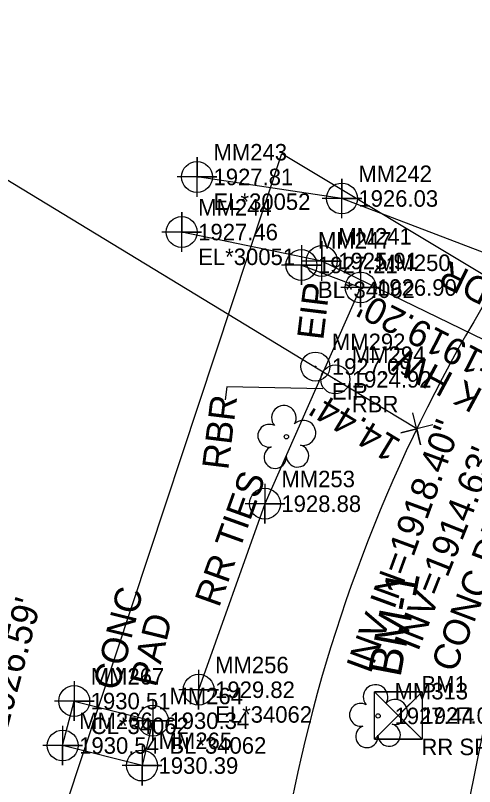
# Model space of a CAD drawing. Extents: x 1004514 to 1005247, y 553695 to 554706.
# Drawn here: x 1004934 to 1005003.6, y 554190.9 to 554307.9 of the extents above; entities that cross this region are included whole.
import ezdxf

# ---------------------------------------------------------------- set-up
doc = ezdxf.new("R2010")
doc.units = 0
for name, color, linetype in [('CTL Vertical Benchmark CELL', 7, 'Continuous'), ('CTL Vertical Benchmark Cogo Comment', 7, 'Continuous'), ('CTL Vertical Benchmark Cogo Elevation', 7, 'Continuous'), ('CTL Vertical Benchmark Cogo Number', 7, 'Continuous'), ('CTL Vertical Benchmark Text', 7, 'Continuous'), ('Exist Other Culture Area Outline', 7, 'Continuous'), ('Exist Other Culture Area Outline Cogo Comment', 7, 'Continuous'), ('Exist Other Culture Area Outline Cogo Elevation', 7, 'Continuous'), ('Exist Other Culture Area Outline Cogo Number', 7, 'Continuous'), ('Exist Other Culture Area Outline Cogo Point CELL', 7, 'Continuous'), ('Exist Other Culture Area Outline Text', 7, 'Continuous'), ('Exist Property Corner CELL', 7, 'Continuous'), ('Exist Property Iron Pin CELL', 7, 'Continuous'), ('Exist Property Iron Pin Cogo Comment', 7, 'Continuous'), ('Exist Property Iron Pin Cogo Elevation', 7, 'Continuous'), ('Exist Property Iron Pin Cogo Number', 7, 'Continuous'), ('Exist Property Iron Pin Leader', 7, 'Continuous'), ('Exist Property Iron Pin Text', 7, 'Continuous'), ('Exist Property Line', 7, 'Continuous'), ('Exist Property Line Text', 7, 'Continuous'), ('Exist Right of Way Line', 7, 'Continuous'), ('Exist Roads EOP', 7, 'Continuous'), ('Exist Roads Soil', 7, 'Continuous'), ('Exist Roads Soil Cogo Comment', 7, 'Continuous'), ('Exist Roads Soil Cogo Elevation', 7, 'Continuous'), ('Exist Roads Soil Cogo Number', 7, 'Continuous'), ('Exist Roads Soil Cogo Point CELL', 7, 'Continuous'), ('Exist Roads Soil Text', 7, 'Continuous'), ('Exist Structure Major Bridge WW Text', 7, 'Continuous'), ('Exist Structure Minor Drop Inlet Text', 7, 'Continuous'), ('Exist Structure Minor Drop Inlet Top Elevation', 7, 'Continuous'), ('Exist Structure Minor Pipes CMP 30 Inch Invert', 7, 'Continuous'), ('Exist Structure Minor Pipes RCP 15 Inch Invert', 7, 'Continuous'), ('Exist Utilities Telephone UG FO SUE LOS C', 7, 'Continuous'), ('Exist Vegetation Tree CELL', 7, 'Continuous'), ('Exist Vegetation Tree Cogo Elevation', 7, 'Continuous'), ('Exist Vegetation Tree Cogo Number', 7, 'Continuous'), ('Old_Level_3', 7, 'Continuous')]:
    doc.layers.add(name, color=color, linetype=linetype)

msp = doc.modelspace()

# ---------------------------------------------------------------- linework, layer by layer
at = {"layer": 'CTL Vertical Benchmark CELL'}
msp.add_line((1004992.06, 554201.69), (1004992.06, 554201.69), dxfattribs=at)
msp.add_lwpolyline([(1004988.46, 554205.27), (1004995.65, 554205.27), (1004995.65, 554198.09), (1004988.46, 554198.09)], close=True, dxfattribs=at)
for points in [[(1004995.65, 554205.27), (1004988.46, 554198.09), (1004992.06, 554201.68), (1004995.65, 554198.09), (1004988.46, 554205.27)], [(1004992.06, 554201.68), (1004995.65, 554205.27), (1004988.46, 554205.27), (1004992.06, 554201.68)], [(1004992.06, 554201.68), (1004988.46, 554198.09), (1004995.65, 554198.09), (1004992.06, 554201.68)]]:
    msp.add_lwpolyline(points, dxfattribs=at)
at = {"layer": 'Exist Other Culture Area Outline'}
for points in [[(1004977.38, 554270.02), (1004986.34, 554266.61), (1004971.84, 554233.82), (1004961.8, 554205.61)], [(1004954.87, 554200.91), (1004953.22, 554194.11), (1004941.19, 554197.15), (1004942.94, 554203.89), (1004954.87, 554200.91)]]:
    msp.add_lwpolyline(points, dxfattribs=at)
at = {"layer": 'Exist Other Culture Area Outline Cogo Point CELL'}
for points in [[(1004977.38, 554273.02), (1004977.38, 554267.02), (1004977.38, 554270.02), (1004980.38, 554270.02), (1004974.38, 554270.02)], [(1004986.34, 554269.61), (1004986.34, 554263.61), (1004986.34, 554266.61), (1004989.34, 554266.61), (1004983.34, 554266.61)], [(1004971.84, 554236.82), (1004971.84, 554230.82), (1004971.84, 554233.82), (1004974.84, 554233.82), (1004968.84, 554233.82)], [(1004961.8, 554208.61), (1004961.8, 554202.61), (1004961.8, 554205.61), (1004964.8, 554205.61), (1004958.8, 554205.61)], [(1004942.94, 554206.89), (1004942.94, 554200.89), (1004942.94, 554203.89), (1004945.94, 554203.89), (1004939.94, 554203.89)], [(1004954.87, 554203.91), (1004954.87, 554197.91), (1004954.87, 554200.91), (1004957.87, 554200.91), (1004951.87, 554200.91)], [(1004941.19, 554200.15), (1004941.19, 554194.15), (1004941.19, 554197.15), (1004944.19, 554197.15), (1004938.19, 554197.15)], [(1004953.22, 554197.11), (1004953.22, 554191.11), (1004953.22, 554194.11), (1004956.22, 554194.11), (1004950.22, 554194.11)]]:
    msp.add_lwpolyline(points, dxfattribs=at)
for centre in [(1004977.38, 554270.02), (1004986.34, 554266.61), (1004971.84, 554233.82), (1004961.8, 554205.61), (1004942.94, 554203.89), (1004954.87, 554200.91), (1004941.19, 554197.15), (1004953.22, 554194.11)]:
    msp.add_circle(centre, 2.34, dxfattribs=at)
at = {"layer": 'Exist Property Corner CELL'}
msp.add_line((1004994.85, 554245.18), (1004994.85, 554245.18), dxfattribs=at)
msp.add_lwpolyline([(1004997.28, 554245.77), (1004992.42, 554244.59), (1004994.85, 554245.18), (1004995.44, 554242.75), (1004994.26, 554247.61)], dxfattribs=at)
at = {"layer": 'Exist Property Iron Pin CELL'}
for centre, radius in [((1004979.49, 554254.62), 2.2), ((1004979.49, 554254.62), 0.0707), ((1004982.51, 554252.68), 2.2), ((1004982.51, 554252.68), 0.0707)]:
    msp.add_circle(centre, radius, dxfattribs=at)
at = {"layer": 'Exist Property Iron Pin Leader'}
msp.add_lwpolyline([(1004980.63, 554251.22), (1004966.05, 554251.54), (1004965.81, 554249.57)], dxfattribs=at)
at = {"layer": 'Exist Property Line'}
for p, q in [((1004982.51, 554252.68), (1004850.41, 554332.98)), ((1004994.85, 554245.18), (1004982.51, 554252.68))]:
    msp.add_line(p, q, dxfattribs=at)
at = {"layer": 'Exist Right of Way Line'}
msp.add_arc((1005209.2, 554141.74), 238, 143.2645, 181.1585, dxfattribs=at)
at = {"layer": 'Exist Roads EOP'}
msp.add_spline([(1005026.38, 554243.67), (1005017.05, 554225.79), (1005004.48, 554185.7), (1005001.44, 554147.87), (1005001.03, 554103.61), (1005002.79, 554054.52)], degree=3, dxfattribs=at)
at = {"layer": 'Exist Roads Soil'}
for points in [[(1005035.48, 554262), (1005019.75, 554266.28), (1004983.51, 554280.11), (1004961.55, 554283.38)], [(1005026.92, 554247.39), (1005013.88, 554254.38), (1004980.46, 554270.63), (1004959.23, 554275.02)]]:
    msp.add_lwpolyline(points, dxfattribs=at)
at = {"layer": 'Exist Roads Soil Cogo Point CELL'}
for points in [[(1004961.55, 554280.38), (1004961.55, 554286.38), (1004961.55, 554283.38), (1004964.55, 554283.38), (1004958.55, 554283.38)], [(1004983.51, 554277.11), (1004983.51, 554283.11), (1004983.51, 554280.11), (1004986.51, 554280.11), (1004980.51, 554280.11)], [(1004959.23, 554272.02), (1004959.23, 554278.02), (1004959.23, 554275.02), (1004962.23, 554275.02), (1004956.23, 554275.02)], [(1004980.46, 554267.63), (1004980.46, 554273.63), (1004980.46, 554270.63), (1004983.46, 554270.63), (1004977.46, 554270.63)]]:
    msp.add_lwpolyline(points, dxfattribs=at)
for centre in [(1004961.55, 554283.38), (1004983.51, 554280.11), (1004959.23, 554275.02), (1004980.46, 554270.63)]:
    msp.add_circle(centre, 2.34, dxfattribs=at)
at = {"layer": 'Exist Utilities Telephone UG FO SUE LOS C'}
msp.add_lwpolyline([(1004993.35, 553880.97), (1004999.91, 553935.31), (1005000.5, 553983.29), (1004999.33, 554031.27), (1004996.57, 554081.46), (1004996.43, 554140.05), (1004998.71, 554168.32), (1005009.15, 554220.25), (1005037.11, 554266.75), (1005065.19, 554302.19)], dxfattribs=at)
at = {"layer": 'Exist Vegetation Tree CELL'}
for p, q in [((1004975.1, 554243.98), (1004975.1, 554243.98)), ((1004988.99, 554201.64), (1004988.99, 554201.64))]:
    msp.add_line(p, q, dxfattribs=at)
for centre in [(1004975.1, 554243.98), (1004988.99, 554201.64)]:
    msp.add_circle(centre, 0.326, dxfattribs=at)
for centre, radius, start, end in [((1004974.72, 554246.85), 1.86, 330.1651, 219.7134), ((1004977.65, 554244.57), 1.9, 257.1011, 134.1999), ((1004972.5, 554244.13), 1.73, 62.6636, 279.3457), ((1004976.78, 554241.08), 1.7, 181.2822, 74.56), ((1004973.4, 554240.86), 1.69, 111.5671, 6.231), ((1004988.61, 554204.52), 1.86, 330.1651, 219.7134), ((1004991.54, 554202.23), 1.9, 257.1011, 134.1999), ((1004986.39, 554201.8), 1.73, 62.6636, 279.3457), ((1004987.29, 554198.52), 1.69, 111.5671, 6.231), ((1004990.67, 554198.74), 1.7, 181.2822, 74.56)]:
    msp.add_arc(centre, radius, start, end, dxfattribs=at)
at = {"layer": 'Old_Level_3'}
for p, q in [((1004908.04, 554086.33), (1004974.39, 554286.95)), ((1004974.39, 554286.95), (1005076.11, 554225.78))]:
    msp.add_line(p, q, dxfattribs=at)

# ---------------------------------------------------------------- texts
at = {"layer": 'CTL Vertical Benchmark Cogo Comment'}
msp.add_text('RR SPIKE IN BASE OF DBL 16" FIR', height=2.5, dxfattribs=at).set_placement((1004995.56, 554195.69))
at = {"layer": 'CTL Vertical Benchmark Cogo Elevation'}
msp.add_text('1927.07', height=2.5, dxfattribs=at).set_placement((1004995.56, 554200.44))
at = {"layer": 'CTL Vertical Benchmark Cogo Number'}
msp.add_text('BM1', height=2.5, dxfattribs=at).set_placement((1004995.56, 554205.19))
at = {"layer": 'CTL Vertical Benchmark Text'}
msp.add_text('BM-1', height=5, rotation=79.2045, dxfattribs=at).set_placement((1004992.36, 554207.37))
at = {"layer": 'Exist Other Culture Area Outline Cogo Comment'}
for s, p in [('BL*34062', (1004979.88, 554265.02)), ('EL*34062', (1004964.3, 554200.61)), ('CL*34062', (1004945.44, 554198.89)), ('BL*34062', (1004957.37, 554195.91))]:
    msp.add_text(s, height=2.5, dxfattribs=at).set_placement(p)
at = {"layer": 'Exist Other Culture Area Outline Cogo Elevation'}
for s, p in [('1927.21', (1004979.88, 554268.77)), ('1926.90', (1004988.84, 554265.36)), ('1928.88', (1004974.34, 554232.57)), ('1929.82', (1004964.3, 554204.36)), ('1930.51', (1004945.44, 554202.64)), ('1930.34', (1004957.37, 554199.66)), ('1930.54', (1004943.69, 554195.9)), ('1930.39', (1004955.72, 554192.86))]:
    msp.add_text(s, height=2.5, dxfattribs=at).set_placement(p)
at = {"layer": 'Exist Other Culture Area Outline Cogo Number'}
for s, p in [('MM247', (1004979.88, 554272.52)), ('MM250', (1004988.84, 554269.11)), ('MM253', (1004974.34, 554236.32)), ('MM256', (1004964.3, 554208.11)), ('MM267', (1004945.44, 554206.39)), ('MM264', (1004957.37, 554203.41)), ('MM266', (1004943.69, 554199.65)), ('MM265', (1004955.72, 554196.61))]:
    msp.add_text(s, height=2.5, dxfattribs=at).set_placement(p)
at = {"layer": 'Exist Other Culture Area Outline Text'}
for s, rotation, p in [('RR TIES', 70.3102, (1004964.88, 554217.95)), ('CONC', 76.1218, (1004949.65, 554205.32)), ('PAD', 76.1218, (1004955.2, 554205.9))]:
    msp.add_text(s, height=4, rotation=rotation, dxfattribs=at).set_placement(p)
at = {"layer": 'Exist Property Iron Pin Cogo Comment'}
for s, p in [('EIP', (1004981.99, 554249.62)), ('RBR', (1004985.01, 554247.68))]:
    msp.add_text(s, height=2.5, dxfattribs=at).set_placement(p)
at = {"layer": 'Exist Property Iron Pin Cogo Elevation'}
for s, p in [('1927.09', (1004981.99, 554253.37)), ('1924.92', (1004985.01, 554251.43))]:
    msp.add_text(s, height=2.5, dxfattribs=at).set_placement(p)
at = {"layer": 'Exist Property Iron Pin Cogo Number'}
for s, p in [('MM292', (1004981.99, 554257.12)), ('MM294', (1004985.01, 554255.18))]:
    msp.add_text(s, height=2.5, dxfattribs=at).set_placement(p)
at = {"layer": 'Exist Property Iron Pin Text'}
for s, p in [('EIP', (1004980.67, 554258.54)), ('RBR', (1004966.28, 554238.85))]:
    msp.add_text(s, height=4, rotation=83.0442, dxfattribs=at).set_placement(p)
at = {"layer": 'Exist Property Line Text'}
msp.add_text("14.44'", height=4, rotation=148.7054, dxfattribs=at).set_placement((1004992.69, 554243.36))
at = {"layer": 'Exist Roads Soil Cogo Comment'}
for s, p in [('EL*30052', (1004964.05, 554278.38)), ('EL*30051', (1004961.73, 554270.02))]:
    msp.add_text(s, height=2.5, dxfattribs=at).set_placement(p)
at = {"layer": 'Exist Roads Soil Cogo Elevation'}
for s, p in [('1927.81', (1004964.05, 554282.13)), ('1926.03', (1004986.01, 554278.86)), ('1927.46', (1004961.73, 554273.77)), ('1925.91', (1004982.96, 554269.38))]:
    msp.add_text(s, height=2.5, dxfattribs=at).set_placement(p)
at = {"layer": 'Exist Roads Soil Cogo Number'}
for s, p in [('MM243', (1004964.05, 554285.88)), ('MM242', (1004986.01, 554282.61)), ('MM244', (1004961.73, 554277.52)), ('MM241', (1004982.96, 554273.13))]:
    msp.add_text(s, height=2.5, dxfattribs=at).set_placement(p)
at = {"layer": 'Exist Roads Soil Text'}
msp.add_text('GR DR', height=4, rotation=154.0689, dxfattribs=at).set_placement((1005015.09, 554263.25))
at = {"layer": 'Exist Structure Major Bridge WW Text'}
msp.add_text('BLK HW', height=4, rotation=151.7681, dxfattribs=at).set_placement((1005010.84, 554247.92))
at = {"layer": 'Exist Structure Minor Drop Inlet Text'}
msp.add_text('CONC DI', height=4, rotation=69.358, dxfattribs=at).set_placement((1005000.68, 554208.07))
at = {"layer": 'Exist Structure Minor Drop Inlet Top Elevation'}
msp.add_text('INV IN=1918.40"', height=4, rotation=69.8918, dxfattribs=at).set_placement((1004987.84, 554207.89))
at = {"layer": 'Exist Structure Minor Pipes CMP 30 Inch Invert'}
msp.add_text("INV=1914.63'", height=4, rotation=68.3068, dxfattribs=at).set_placement((1004995.04, 554211.29))
at = {"layer": 'Exist Structure Minor Pipes RCP 15 Inch Invert'}
for s, rotation, p in [("INV=1919.20'", 153.0004, (1005016.17, 554251.24)), ("INV=1926.59'", 75.0983, (1004929.64, 554187.59))]:
    msp.add_text(s, height=4, rotation=rotation, dxfattribs=at).set_placement(p)
at = {"layer": 'Exist Vegetation Tree Cogo Elevation'}
msp.add_text('1927.44', height=2.5, dxfattribs=at).set_placement((1004991.49, 554200.39))
at = {"layer": 'Exist Vegetation Tree Cogo Number'}
msp.add_text('MM313', height=2.5, dxfattribs=at).set_placement((1004991.49, 554204.14))

doc.saveas('drawing.dxf')
